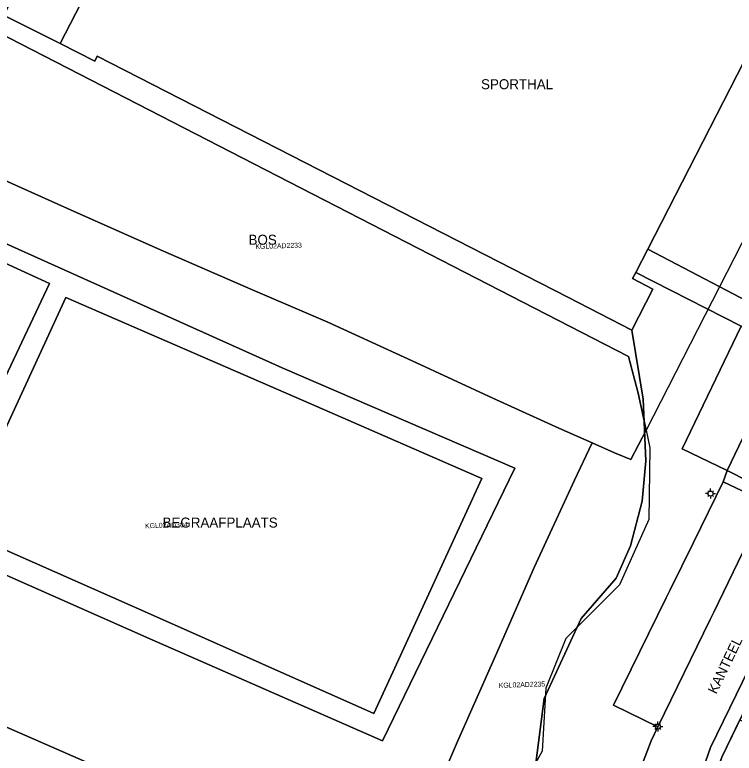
# Model space of a CAD drawing. Extents: x 124901 to 125496, y 515369 to 515789.
# Drawn here: x 125098.9 to 125170.8, y 515436.5 to 515510.4 of the extents above; entities that cross this region are included whole.
import ezdxf

# ---------------------------------------------------------------- set-up
doc = ezdxf.new("R2010")
doc.units = 0
for name, color, linetype in [('Gebouw', 7, 'Continuous'), ('Lichtmast', 7, 'Continuous'), ('Onbegroeid terrein', 7, 'Continuous'), ('Parkeren', 7, 'Continuous'), ('Perceelnummers', 7, 'Continuous'), ('Perceelsgrenzen', 7, 'Continuous'), ('Teksten', 7, 'Continuous'), ('Vegetatie', 7, 'Continuous'), ('Voetpad', 7, 'Continuous'), ('Wegen lokale weg', 7, 'Continuous')]:
    doc.layers.add(name, color=color, linetype=linetype)

msp = doc.modelspace()

# ---------------------------------------------------------------- linework, layer by layer
at = {"layer": 'Gebouw'}
msp.add_lwpolyline([(125114.85, 515529.67), (125103.421, 515507.503), (125106.866, 515505.735), (125107.13, 515506.248), (125154.166, 515482.121), (125160.588, 515478.821), (125162.691, 515482.931), (125160.664, 515483.99), (125160.973, 515484.593), (125162.176, 515486.941), (125173.17, 515508.4)], dxfattribs=at)
at = {"layer": 'Lichtmast'}
for p, q in [((125168.162, 515462.475), (125167.962, 515462.474)), ((125168.25, 515462.686), (125168.18, 515462.757)), ((125168.462, 515462.774), (125168.462, 515462.974)), ((125168.674, 515462.686), (125168.745, 515462.758)), ((125168.762, 515462.474), (125168.962, 515462.474)), ((125168.25, 515462.262), (125168.178, 515462.191)), ((125168.462, 515462.174), (125168.462, 515461.974)), ((125168.674, 515462.262), (125168.744, 515462.191)), ((125163.178, 515439.474), (125163.178, 515439.674)), ((125162.878, 515439.175), (125162.678, 515439.174)), ((125162.966, 515438.962), (125162.894, 515438.891)), ((125162.966, 515439.386), (125162.896, 515439.457)), ((125163.178, 515438.874), (125163.178, 515438.674)), ((125163.39, 515439.386), (125163.461, 515439.458)), ((125163.39, 515438.962), (125163.46, 515438.891)), ((125163.478, 515439.174), (125163.678, 515439.174))]:
    msp.add_line(p, q, dxfattribs=at)
for centre in [(125168.462, 515462.474), (125163.178, 515439.174)]:
    msp.add_circle(centre, 0.25, dxfattribs=at)
at = {"layer": 'Onbegroeid terrein'}
for points in [[(125124.833, 515554.591), (125122.838, 515555.608), (125121.475, 515556.282), (125119.632, 515552.771), (125111.363, 515536.58), (125105.393, 515525.115), (125098.416, 515511.737), (125097.735, 515510.333), (125103.421, 515507.503), (125114.85, 515529.67), (125112.17, 515531.03), (125119.76, 515545.9), (125120.26, 515545.65)], [(125080.282, 515456.092), (125081.048, 515455.692), (125078.894, 515451.482), (125075.825, 515453.028), (125077.989, 515457.288), (125078.688, 515456.923), (125081.984, 515463.623), (125091.01, 515459.258), (125095.47, 515468.968), (125084.315, 515473.966), (125085.41, 515476.184), (125096.5, 515471.175), (125102.358, 515483.481), (125094.192, 515487.231), (125094.871, 515488.854), (125125.622, 515475.053), (125148.897, 515465.033), (125135.651, 515437.732), (125112.605, 515447.846), (125090.368, 515457.679), (125082.745, 515461.201)], [(125145.588, 515463.984), (125128.553, 515471.424), (125103.994, 515482.094), (125093.293, 515458.891), (125112.438, 515450.415), (125134.768, 515440.479)], [(125212.378, 515407.217), (125218.773, 515420.602), (125228.705, 515441.027), (125231.369, 515446.506), (125208.757, 515457.227), (125207.246, 515457.999), (125185.331, 515468.649), (125174.743, 515446.788), (125169.594, 515436.119), (125169.208, 515435.054), (125169.078, 515434.302), (125169.052, 515433.637), (125169.143, 515433.015), (125169.246, 515432.293), (125171.72, 515424.504), (125175.501, 515422.7), (125184.563, 515418.371), (125187.6, 515416.92), (125188.955, 515416.229), (125189.83, 515418.039), (125192.711, 515416.656), (125201.09, 515412.635)]]:
    msp.add_lwpolyline(points, close=True, dxfattribs=at)
msp.add_lwpolyline([(125095.075, 515423.399), (125099.204, 515432.322), (125110.655, 515427.43), (125122.127, 515422.267), (125130.143, 515418.768), (125132.577, 515423.948), (125138.495, 515423.574), (125142.807, 515424.652), (125143.845, 515425.555), (125147.032, 515428.328), (125150.834, 515434.472), (125151.815, 515441.972), (125155.511, 515449.984), (125159.029, 515454.001), (125160.437, 515457.237), (125161.603, 515461.705), (125161.995, 515465.762), (125161.709, 515471.904), (125160.588, 515478.821), (125154.166, 515482.121), (125107.13, 515506.248), (125106.866, 515505.735), (125103.421, 515507.503), (125097.735, 515510.333)], dxfattribs=at)
at = {"layer": 'Parkeren'}
for points in [[(125170.117, 515464.778), (125175.957, 515476.948), (125171.502, 515479.221), (125165.609, 515466.941)], [(125174.09, 515461.571), (125169.717, 515463.642), (125166.739, 515457.588), (125164.401, 515452.835), (125164.008, 515452.033), (125158.757, 515441.318), (125163.171, 515439.155), (125168.42, 515449.871), (125168.778, 515450.627)]]:
    msp.add_lwpolyline(points, close=True, dxfattribs=at)
at = {"layer": 'Perceelsgrenzen'}
for points in [[(125160.233, 515476.176), (125097.068, 515508.659), (125097.847, 515510.446), (125109.338, 515532.513), (125123.013, 515559.046), (125125.056, 515562.995), (125159.741, 515545.245), (125158.376, 515542.562), (125182.469, 515530.005), (125186.05, 515515.764), (125185.338, 515514.373), (125180.365, 515504.659), (125162.009, 515468.834), (125161.231, 515472.504)], [(125160.233, 515476.176), (125161.231, 515472.504), (125162.009, 515468.834), (125160.498, 515465.884), (125158.866, 515466.538), (125156.614, 515467.536), (125153.276, 515469.016), (125146.681, 515472.032), (125138.626, 515475.74), (125130.175, 515479.614), (125122.47, 515482.934), (125113.746, 515486.742), (125104.802, 515490.703), (125096.909, 515494.22), (125091.746, 515496.538), (125092.407, 515498.091), (125093.621, 515500.609), (125094.875, 515503.631), (125097.068, 515508.659)], [(125137.489, 515424.795), (125139.694, 515429.575), (125143.158, 515437.682), (125146.958, 515446.252), (125150.814, 515455.066), (125154.859, 515463.81), (125156.614, 515467.536), (125158.866, 515466.538), (125160.498, 515465.884), (125162.009, 515468.834), (125162.385, 515467.065), (125162.267, 515459.869), (125159.338, 515453.361), (125153.997, 515447.989), (125151.969, 515443.01), (125151.625, 515436.721), (125147.022, 515428.44), (125140.851, 515425.095)], [(125122.146, 515421.609), (125114.357, 515425.363), (125106.637, 515429.073), (125099.561, 515432.482), (125096.85, 515426.85), (125095.213, 515423.448), (125090.844, 515425.514), (125066.092, 515437.217), (125067.518, 515440.431), (125068.705, 515443.058), (125070.733, 515447.672), (125072.164, 515450.432), (125075.956, 515448.765), (125083.957, 515445.274), (125097.173, 515439.469), (125108.933, 515434.353), (125120.613, 515429.23), (125132.648, 515423.861), (125129.798, 515417.933)], [(125171.391, 515439.843), (125184.28, 515433.63), (125194.19, 515428.85), (125191.98, 515424.25), (125182.06, 515429.04), (125169.26, 515435.197), (125169.594, 515436.119)]]:
    msp.add_lwpolyline(points, close=True, dxfattribs=at)
for points in [[(125180.365, 515504.659), (125162.009, 515468.834), (125162.385, 515467.065), (125162.267, 515459.869), (125159.338, 515453.361), (125153.997, 515447.989), (125151.969, 515443.01), (125151.625, 515436.721), (125147.022, 515428.44), (125140.851, 515425.095), (125137.489, 515424.795), (125136.248, 515422.103), (125133.299, 515423.571), (125132.648, 515423.861), (125129.798, 515417.933), (125127.09, 515412.3), (125123.6, 515405.04), (125120.86, 515399.36), (125116.204, 515389.664), (125108.472, 515393.42), (125100.776, 515397.159), (125093.068, 515400.904)], [(125096.909, 515494.22), (125104.802, 515490.703), (125113.746, 515486.742), (125122.47, 515482.934), (125130.175, 515479.614), (125138.626, 515475.74), (125146.681, 515472.032), (125153.276, 515469.016), (125156.614, 515467.536), (125154.859, 515463.81), (125150.814, 515455.066), (125146.958, 515446.252), (125143.158, 515437.682), (125139.694, 515429.575), (125137.489, 515424.795), (125136.248, 515422.103), (125133.299, 515423.571), (125132.648, 515423.861), (125120.613, 515429.23), (125108.933, 515434.353), (125097.173, 515439.469)], [(125170.86, 515427.213), (125169.246, 515432.293), (125169.143, 515433.015), (125169.052, 515433.637), (125169.078, 515434.302), (125169.208, 515435.054), (125169.26, 515435.197), (125169.594, 515436.119), (125171.391, 515439.843)]]:
    msp.add_lwpolyline(points, dxfattribs=at)
at = {"layer": 'Vegetatie'}
for points in [[(125162.176, 515486.941), (125174.275, 515480.584), (125175.722, 515483.384), (125173.995, 515484.25), (125172.269, 515485.093), (125181.593, 515503.982), (125176.381, 515506.752), (125173.17, 515508.4)], [(125170.117, 515464.778), (125169.717, 515463.642), (125174.09, 515461.571), (125174.524, 515462.559)]]:
    msp.add_lwpolyline(points, close=True, dxfattribs=at)
msp.add_lwpolyline([(125161.765, 515435.74), (125162.08, 515436.601), (125162.519, 515437.74), (125163.171, 515439.155), (125158.757, 515441.318), (125164.008, 515452.033), (125164.401, 515452.835), (125166.739, 515457.588), (125169.717, 515463.642), (125170.117, 515464.778), (125165.609, 515466.941), (125171.502, 515479.221), (125160.973, 515484.593), (125160.664, 515483.99), (125162.691, 515482.931), (125160.588, 515478.821), (125161.709, 515471.904), (125161.995, 515465.762), (125161.603, 515461.705), (125160.437, 515457.237), (125159.029, 515454.001), (125155.511, 515449.984), (125151.815, 515441.972), (125150.834, 515434.472)], dxfattribs=at)
at = {"layer": 'Voetpad'}
for points in [[(125084.315, 515473.966), (125095.47, 515468.968), (125091.01, 515459.258), (125081.984, 515463.623), (125078.688, 515456.923), (125080.282, 515456.092), (125082.745, 515461.201), (125090.368, 515457.679), (125112.605, 515447.846), (125135.651, 515437.732), (125148.897, 515465.033), (125125.622, 515475.053), (125094.871, 515488.854), (125094.192, 515487.231), (125102.358, 515483.481), (125096.5, 515471.175), (125085.41, 515476.184)], [(125174.275, 515480.584), (125162.176, 515486.941), (125160.973, 515484.593), (125171.502, 515479.221), (125175.957, 515476.948), (125177.012, 515479.146)], [(125134.768, 515440.479), (125112.438, 515450.415), (125093.293, 515458.891), (125103.994, 515482.094), (125128.553, 515471.424), (125145.588, 515463.984)], [(125167.769, 515434.757), (125167.61, 515433.758), (125167.642, 515432.996), (125167.965, 515431.692), (125170.351, 515424.118), (125170.572, 515423.444), (125174.885, 515421.409), (125175.501, 515422.7), (125171.72, 515424.504), (125169.246, 515432.293), (125169.143, 515433.015), (125169.052, 515433.637), (125169.078, 515434.302), (125169.208, 515435.054), (125169.594, 515436.119), (125174.743, 515446.788), (125185.331, 515468.649), (125184.024, 515469.175), (125173.585, 515447.618), (125168.466, 515437.087), (125167.943, 515435.636)]]:
    msp.add_lwpolyline(points, close=True, dxfattribs=at)
at = {"layer": 'Wegen lokale weg'}
for points in [[(125175.957, 515476.948), (125170.117, 515464.778), (125174.524, 515462.559)], [(125174.09, 515461.571), (125168.778, 515450.627), (125168.42, 515449.871), (125163.171, 515439.155), (125162.519, 515437.74), (125162.08, 515436.601), (125161.765, 515435.74)], [(125171.736, 515419.886), (125170.572, 515423.444), (125170.351, 515424.118), (125167.965, 515431.692), (125167.642, 515432.996), (125167.61, 515433.758), (125167.769, 515434.757), (125167.943, 515435.636), (125168.466, 515437.087), (125173.585, 515447.618)]]:
    msp.add_lwpolyline(points, dxfattribs=at)

# ---------------------------------------------------------------- texts
at = {"layer": 'Perceelnummers'}
for s, rotation, p in [('KGL02AD2233', 1.82948, (125122.946, 515486.936)), ('KGL02AD304', 1.63116, (125111.907, 515459.002)), ('KGL02AD2235', 1.82976, (125147.28, 515443.038))]:
    msp.add_text(s, height=0.5, rotation=rotation, dxfattribs=at).set_placement(p)
at = {"layer": 'Teksten'}
for s, p in [('SPORTHAL', (125145.505, 515502.928)), ('BOS', (125122.252, 515487.37)), ('BEGRAAFPLAATS', (125113.651, 515459.076))]:
    msp.add_text(s, height=1, dxfattribs=at).set_placement(p)
msp.add_text('KANTEEL', height=1, rotation=64.3, dxfattribs=at).set_placement((125169.032, 515442.347))

doc.saveas('drawing.dxf')
